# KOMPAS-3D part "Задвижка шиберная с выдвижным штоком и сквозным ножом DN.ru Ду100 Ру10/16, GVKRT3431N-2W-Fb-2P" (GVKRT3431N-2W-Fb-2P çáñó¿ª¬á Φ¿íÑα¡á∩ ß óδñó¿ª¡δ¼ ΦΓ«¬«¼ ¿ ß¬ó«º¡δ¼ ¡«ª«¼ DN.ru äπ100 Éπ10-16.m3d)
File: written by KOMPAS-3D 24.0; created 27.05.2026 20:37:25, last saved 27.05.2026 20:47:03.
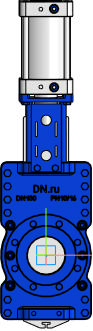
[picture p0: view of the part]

Document properties: Автор: DN.ru; Полное имя файла: C:\Работа\ГОТОВЫЕ ИСХОДНИКИ\GVKRT3431N-2W-Fb-2P Задвижка шиберная со сквозным ножом DN.ru Ду100-250 Ру16\DN100\GVKRT3431N-2W-Fb-2P Задвижка шиберная с выдвижным штоком и сквозным ножом DN.ru Ду100 Ру10-16.m3d

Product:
- Part/product: Задвижка шиберная с выдвижным штоком и сквозным ножом DN.ru Ду100 Ру10/16  | designation GVKRT3431N-2W-Fb-2P
    Масса: 25
    Раздел спецификации: Прочие изделия
    Примечание: D040-08530

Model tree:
1. Операция без истории:1

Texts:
  GVKRT3431N-2W-Fb-2P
